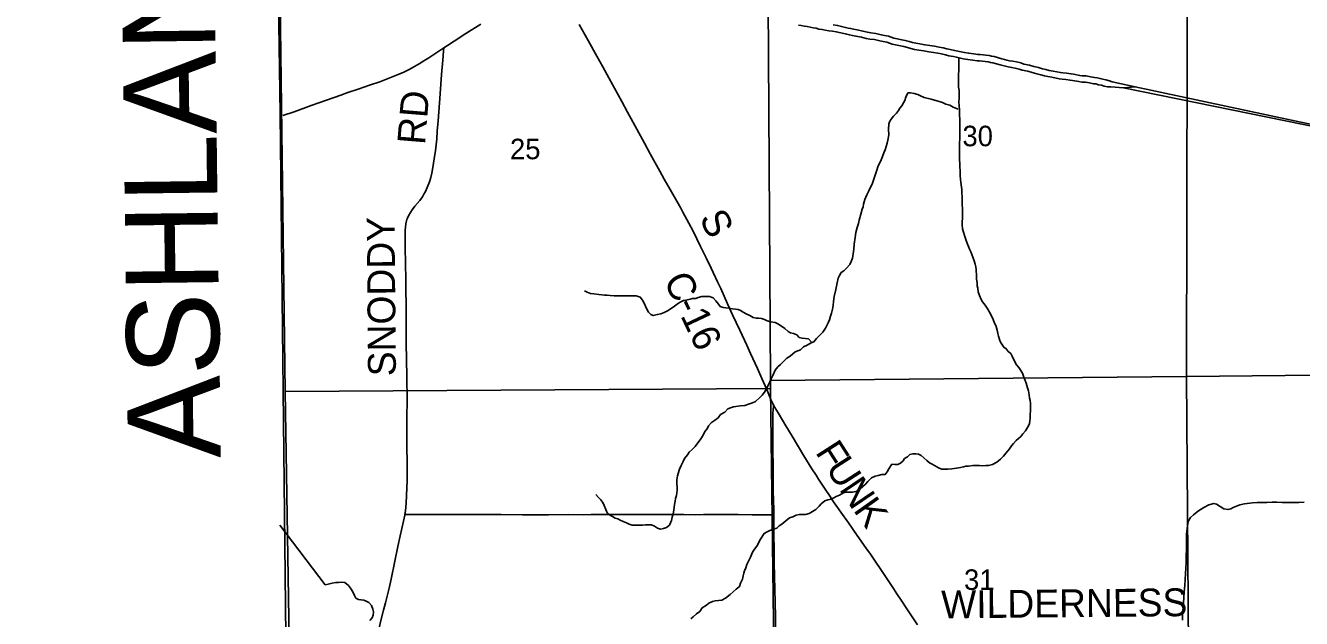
# Model space of a CAD drawing. Extents: x 1985906 to 2360102, y 891258 to 1222054.
# Drawn here: x 2069216 to 2082964, y 996240 to 1002629 of the extents above; entities that cross this region are included whole.
import ezdxf

# ---------------------------------------------------------------- set-up
doc = ezdxf.new("R2010")
doc.units = 0
for name, color, linetype in [('GM_X_Adjacent_County', 7, 'Continuous'), ('GM_X_Adjacent_County_Text', 7, 'Continuous'), ('GM_X_County', 7, 'Continuous'), ('GM_X_County_Road', 7, 'Continuous'), ('GM_X_County_Road_Text', 7, 'Continuous'), ('GM_X_Minor_River', 7, 'Continuous'), ('GM_X_Section', 7, 'Continuous'), ('GM_X_Section_Text', 7, 'Continuous'), ('GM_X_State_Route', 7, 'Continuous'), ('GM_X_Township', 7, 'Continuous'), ('GM_X_Township_Road', 7, 'Continuous'), ('GM_X_Township_Road_Text', 7, 'Continuous')]:
    doc.layers.add(name, color=color, linetype=linetype)

msp = doc.modelspace()

# ---------------------------------------------------------------- linework, layer by layer
at = {"layer": 'GM_X_Adjacent_County'}
msp.add_lwpolyline([(2071861, 1011952), (2071887, 1008769), (2071889, 1006520), (2071959, 1001676), (2072021, 996047), (2072065, 993379), (2071978, 993380), (2071988, 991894), (2071996, 990692), (2072013, 988008), (2072047, 982707), (2072077, 978079), (2072089, 977430), (2072091, 977317), (2072186, 972205), (2071957, 972211), (2068961, 972095)], dxfattribs=at)
at = {"layer": 'GM_X_County'}
msp.add_lwpolyline([(2072047, 982707), (2072013, 988008), (2071996, 990692), (2071988, 991894), (2071978, 993380), (2072065, 993379), (2072021, 996047), (2071959, 1001676), (2071889, 1006520), (2071887, 1008769), (2071861, 1011952)], dxfattribs=at)
at = {"layer": 'GM_X_County_Road'}
for points in [[(2077277, 998539), (2077268, 998556), (2077248, 998600), (2077204, 998706), (2077151, 998826), (2077103, 998932), (2077028, 999096), (2076987, 999185), (2076912, 999348), (2076834, 999512), (2076781, 999632), (2076707, 999795), (2076673, 999869), (2076605, 1000014), (2076551, 1000127), (2076490, 1000249), (2076408, 1000412), (2076362, 1000501), (2076299, 1000617), (2076276, 1000661), (2076219, 1000761), (2076162, 1000861), (2076098, 1000974), (2076050, 1001060), (2075946, 1001246), (2075884, 1001362), (2075782, 1001550), (2075703, 1001694), (2075641, 1001809), (2075521, 1002024), (2075435, 1002182), (2075373, 1002297), (2075278, 1002468), (2075182, 1002640)], [(2077278, 997358), (2077278, 997416), (2077276, 997515), (2077273, 997613), (2077271, 997777), (2077270, 997876), (2077268, 998056), (2077268, 998151), (2077269, 998285), (2077269, 998449), (2077270, 998493), (2077275, 998523), (2077277, 998539)], [(2078827, 996171), (2078711, 996346), (2078651, 996436), (2078605, 996505), (2078567, 996563), (2078512, 996649), (2078438, 996759), (2078365, 996867), (2078319, 996934), (2078272, 997002), (2078178, 997136), (2078131, 997203), (2078083, 997270), (2078000, 997385), (2077957, 997445), (2077923, 997496), (2077877, 997564), (2077832, 997633), (2077759, 997743), (2077734, 997784), (2077689, 997854), (2077603, 997993), (2077476, 998203), (2077408, 998315), (2077324, 998456), (2077291, 998512), (2077277, 998539)], [(2077298, 996101), (2077296, 996253), (2077292, 996418), (2077290, 996548), (2077287, 996699), (2077284, 996831), (2077281, 997007), (2077279, 997117), (2077278, 997230), (2077278, 997336), (2077278, 997358)]]:
    msp.add_lwpolyline(points, dxfattribs=at)
at = {"layer": 'GM_X_Minor_River'}
msp.add_line((2081048, 1001957), (2081172, 1001968), dxfattribs=at)
for points in [[(2077543, 1002634), (2077575, 1002628), (2077605, 1002622), (2077639, 1002617), (2077671, 1002611), (2077703, 1002605), (2077735, 1002599)], [(2077735, 1002599), (2077765, 1002591), (2077799, 1002585), (2077832, 1002579), (2077870, 1002573), (2077910, 1002568), (2077952, 1002562), (2078064, 1002534), (2078094, 1002528), (2078126, 1002522), (2078164, 1002515), (2078223, 1002503), (2078273, 1002489), (2078315, 1002483), (2078365, 1002477), (2078421, 1002464), (2078457, 1002456), (2078497, 1002448), (2078554, 1002428), (2078678, 1002403), (2078718, 1002391), (2078756, 1002381), (2078796, 1002371), (2078843, 1002363), (2078895, 1002355), (2078949, 1002346), (2078999, 1002338), (2079047, 1002330), (2079087, 1002322), (2079127, 1002312), (2079165, 1002302), (2079214, 1002295), (2079246, 1002287), (2079320, 1002271), (2079368, 1002263), (2079394, 1002259), (2079424, 1002255), (2079470, 1002250), (2079496, 1002248), (2079526, 1002244), (2079557, 1002242), (2079587, 1002238), (2079613, 1002232), (2079639, 1002228), (2079717, 1002205), (2079747, 1002197), (2079775, 1002191), (2079805, 1002183), (2079841, 1002177), (2079878, 1002169), (2079922, 1002159), (2079954, 1002147), (2080016, 1002136), (2080064, 1002122), (2080112, 1002110), (2080156, 1002096), (2080195, 1002088), (2080233, 1002078), (2080275, 1002071), (2080355, 1002055), (2080385, 1002051), (2080425, 1002047), (2080471, 1002039), (2080497, 1002036), (2080566, 1002024), (2080596, 1002020), (2080636, 1002018), (2080680, 1002010), (2080722, 1002002), (2080750, 1001999), (2080778, 1001991), (2080808, 1001985), (2080840, 1001977), (2080874, 1001969), (2080910, 1001968), (2081048, 1001957)], [(2081172, 1001968), (2080925, 1002022), (2080895, 1002034), (2080856, 1002043), (2080823, 1002051), (2080794, 1002057), (2080764, 1002065), (2080733, 1002070), (2080692, 1002077), (2080643, 1002086), (2080602, 1002088), (2080576, 1002091), (2080508, 1002103), (2080482, 1002107), (2080434, 1002115), (2080393, 1002119), (2080366, 1002122), (2080288, 1002137), (2080247, 1002145), (2080210, 1002155), (2080174, 1002162), (2080131, 1002176), (2080082, 1002188), (2080032, 1002202), (2079972, 1002213), (2079941, 1002225), (2079892, 1002236), (2079854, 1002244), (2079819, 1002250), (2079791, 1002257), (2079763, 1002263), (2079736, 1002270), (2079654, 1002295), (2079625, 1002299), (2079598, 1002305), (2079563, 1002310), (2079533, 1002312), (2079503, 1002315), (2079477, 1002317), (2079433, 1002323), (2079404, 1002327), (2079379, 1002330), (2079332, 1002338), (2079261, 1002353), (2079227, 1002361), (2079179, 1002369), (2079144, 1002378), (2079102, 1002389), (2079059, 1002397), (2079010, 1002405), (2078960, 1002413), (2078906, 1002422), (2078853, 1002430), (2078810, 1002438), (2078773, 1002447), (2078736, 1002456), (2078695, 1002469), (2078572, 1002494), (2078515, 1002514), (2078471, 1002522), (2078437, 1002530), (2078377, 1002544), (2078324, 1002551), (2078287, 1002556), (2078238, 1002569), (2078178, 1002581), (2078139, 1002589), (2078107, 1002595), (2078079, 1002601), (2077965, 1002629), (2077919, 1002635)], [(2079274, 1002281), (2079267, 1001966), (2079275, 1001930), (2079277, 1001898), (2079275, 1001843), (2079273, 1001805), (2079275, 1001765), (2079278, 1001719), (2079278, 1001667), (2079282, 1001615), (2079284, 1001568), (2079284, 1001450), (2079282, 1001408), (2079280, 1001364), (2079279, 1001315), (2079279, 1001263), (2079281, 1001221), (2079281, 1001183), (2079283, 1001141), (2079283, 1001101), (2079285, 1001068), (2079287, 1001038), (2079287, 1001012), (2079291, 1000968), (2079294, 1000942), (2079300, 1000888), (2079304, 1000862), (2079306, 1000827), (2079308, 1000783), (2079308, 1000693), (2079310, 1000661), (2079310, 1000629), (2079312, 1000597), (2079311, 1000556), (2079309, 1000510), (2079309, 1000482), (2079311, 1000440), (2079321, 1000404), (2079335, 1000366), (2079349, 1000324), (2079366, 1000273), (2079376, 1000247), (2079386, 1000221), (2079400, 1000189), (2079422, 1000133), (2079437, 1000095), (2079449, 1000056), (2079455, 1000030), (2079459, 1000000), (2079463, 999928), (2079463, 999896), (2079469, 999856), (2079471, 999825), (2079476, 999799), (2079482, 999761), (2079494, 999719), (2079514, 999677), (2079528, 999651), (2079555, 999617), (2079577, 999584), (2079603, 999542), (2079636, 999478), (2079654, 999432), (2079674, 999386), (2079684, 999348), (2079692, 999311), (2079700, 999281), (2079709, 999245), (2079723, 999219), (2079757, 999163), (2079783, 999147), (2079804, 999117), (2079832, 999096), (2079848, 999066), (2079876, 999004), (2079895, 998972), (2079917, 998944), (2079957, 998884), (2079972, 998841), (2079986, 998803), (2079998, 998775), (2080012, 998725), (2080024, 998693), (2080030, 998651), (2080033, 998614), (2080041, 998588), (2080045, 998560), (2080045, 998522), (2080043, 998476), (2080041, 998442), (2080041, 998398), (2080037, 998368), (2080033, 998339), (2080013, 998297), (2079989, 998263), (2079963, 998231), (2079939, 998201), (2079891, 998157), (2079860, 998127), (2079840, 998101), (2079820, 998068)], [(2079265, 1001727), (2079213, 1001749), (2079175, 1001769), (2079134, 1001781), (2079098, 1001801), (2079048, 1001815), (2079011, 1001826), (2078973, 1001836), (2078900, 1001854), (2078860, 1001872), (2078830, 1001886), (2078791, 1001898), (2078753, 1001904), (2078723, 1001902), (2078701, 1001858), (2078689, 1001822), (2078677, 1001794), (2078657, 1001765), (2078635, 1001739), (2078621, 1001713), (2078599, 1001683), (2078570, 1001651), (2078542, 1001621), (2078526, 1001591), (2078518, 1001565), (2078514, 1001513), (2078519, 1001450), (2078509, 1001394), (2078501, 1001362), (2078479, 1001288), (2078463, 1001256), (2078451, 1001219), (2078437, 1001183), (2078400, 1001107), (2078388, 1001069), (2078374, 1001029), (2078360, 1000983), (2078342, 1000932), (2078302, 1000848), (2078284, 1000812), (2078270, 1000780), (2078260, 1000754), (2078246, 1000704), (2078240, 1000677), (2078232, 1000649), (2078216, 1000597), (2078200, 1000533), (2078190, 1000495), (2078176, 1000451), (2078164, 1000398), (2078154, 1000344), (2078145, 1000274), (2078141, 1000218), (2078135, 1000168), (2078127, 1000123), (2078113, 1000087), (2078097, 1000055), (2078061, 1000015), (2078034, 999987), (2078006, 999967), (2077988, 999935), (2077972, 999907), (2077960, 999856), (2077954, 999822), (2077946, 999786), (2077930, 999710), (2077922, 999654), (2077918, 999611), (2077912, 999573), (2077901, 999529), (2077891, 999497), (2077879, 999459), (2077864, 999425), (2077850, 999397), (2077834, 999367), (2077806, 999326), (2077782, 999300), (2077740, 999258), (2077710, 999220), (2077682, 999210), (2077639, 999184), (2077599, 999166), (2077565, 999136), (2077507, 999112), (2077454, 999066), (2077420, 999044), (2077350, 998975), (2077322, 998951), (2077295, 998915), (2077269, 998857), (2077251, 998823), (2077237, 998791), (2077223, 998761), (2077207, 998730), (2077177, 998678), (2077153, 998646), (2077127, 998620), (2077081, 998578), (2077048, 998562), (2077006, 998550), (2076968, 998534)], [(2083373, 1001484), (2081048, 1001957)], [(2081172, 1001968), (2083345, 1001506)], [(2077690, 999213), (2077651, 999252), (2077583, 999260), (2077553, 999266), (2077526, 999298), (2077492, 999309), (2077460, 999319), (2077434, 999331), (2077397, 999363), (2077361, 999389), (2077322, 999415), (2077292, 999429), (2077248, 999437), (2077208, 999447), (2077179, 999461), (2077147, 999473), (2077115, 999477), (2077087, 999477), (2077056, 999483), (2077020, 999504), (2076982, 999524), (2076947, 999542), (2076919, 999558), (2076893, 999568), (2076865, 999572), (2076834, 999576), (2076802, 999582), (2076760, 999586), (2076734, 999590), (2076701, 999600), (2076681, 999626), (2076653, 999664), (2076625, 999694), (2076584, 999711), (2076532, 999711), (2076504, 999709), (2076465, 999697), (2076439, 999689), (2076403, 999689), (2076377, 999681), (2076332, 999671), (2076304, 999665), (2076278, 999653), (2076250, 999636), (2076208, 999604), (2076163, 999574), (2076133, 999554), (2076097, 999538), (2076063, 999524), (2076023, 999514), (2075980, 999504), (2075952, 999514), (2075930, 999542), (2075912, 999574), (2075879, 999643), (2075863, 999671), (2075839, 999701), (2075796, 999715), (2075766, 999715), (2075726, 999717), (2075698, 999715), (2075663, 999717), (2075631, 999715), (2075559, 999715), (2075514, 999721), (2075484, 999723), (2075456, 999725), (2075426, 999727), (2075393, 999731), (2075339, 999739), (2075303, 999741), (2075266, 999755), (2075240, 999770)], [(2076968, 998534), (2076920, 998530), (2076845, 998520), (2076813, 998510), (2076785, 998498), (2076750, 998464), (2076706, 998438), (2076678, 998401), (2076638, 998373), (2076606, 998351), (2076576, 998317), (2076559, 998285), (2076537, 998255), (2076517, 998215), (2076491, 998177), (2076473, 998151), (2076451, 998120), (2076433, 998094), (2076399, 998060), (2076365, 998032), (2076347, 998004), (2076316, 997964), (2076302, 997930), (2076282, 997888), (2076264, 997849), (2076248, 997803), (2076242, 997777), (2076234, 997735), (2076234, 997691), (2076239, 997659), (2076237, 997623), (2076231, 997564), (2076221, 997534), (2076215, 997506), (2076207, 997470), (2076205, 997438), (2076203, 997408), (2076195, 997366), (2076185, 997332), (2076177, 997297), (2076153, 997245), (2076123, 997221), (2076091, 997209), (2076056, 997203), (2076024, 997215), (2075994, 997235), (2075962, 997251), (2075935, 997251), (2075897, 997249), (2075865, 997245), (2075798, 997245), (2075752, 997247), (2075720, 997255), (2075693, 997270), (2075655, 997286), (2075623, 997300), (2075597, 997314), (2075570, 997322), (2075542, 997338), (2075508, 997358), (2075482, 997380), (2075467, 997416), (2075451, 997456), (2075439, 997482), (2075415, 997517), (2075391, 997545), (2075360, 997575)], [(2079820, 998068), (2079784, 998024), (2079752, 997988), (2079722, 997956), (2079680, 997924), (2079635, 997900), (2079593, 997888), (2079563, 997888), (2079531, 997886), (2079494, 997888), (2079460, 997890), (2079422, 997888), (2079375, 997882), (2079347, 997880), (2079321, 997874), (2079291, 997868), (2079247, 997860), (2079198, 997854), (2079152, 997850), (2079116, 997848), (2079089, 997850), (2079061, 997858), (2079035, 997874), (2078986, 997902), (2078956, 997916), (2078926, 997944), (2078865, 997997), (2078837, 998011), (2078809, 998015), (2078777, 998015), (2078746, 998007), (2078718, 997981), (2078688, 997963), (2078672, 997937), (2078642, 997912), (2078614, 997900), (2078583, 997898), (2078551, 997902), (2078519, 997852), (2078499, 997820), (2078479, 997792), (2078441, 997790), (2078402, 997782), (2078370, 997772), (2078332, 997756), (2078290, 997716), (2078266, 997688), (2078239, 997662), (2078209, 997636), (2078167, 997610), (2078123, 997600), (2078089, 997600), (2078056, 997602), (2078030, 997594), (2077986, 997570), (2077952, 997553), (2077925, 997541), (2077895, 997525), (2077859, 997517), (2077829, 997509), (2077789, 997475), (2077768, 997449), (2077732, 997415), (2077694, 997393), (2077658, 997373), (2077620, 997361), (2077579, 997361), (2077553, 997359), (2077521, 997353), (2077483, 997335), (2077446, 997323), (2077410, 997291), (2077364, 997255), (2077338, 997239), (2077310, 997214), (2077263, 997198), (2077235, 997188), (2077207, 997174), (2077173, 997156), (2077137, 997096), (2077097, 997020), (2077070, 996988), (2077050, 996954), (2077026, 996901), (2077002, 996851), (2076988, 996821), (2076976, 996785), (2076962, 996755), (2076954, 996727), (2076948, 996701), (2076940, 996665), (2076920, 996620), (2076910, 996584), (2076874, 996556), (2076842, 996528), (2076808, 996498), (2076759, 996458), (2076719, 996438), (2076647, 996430), (2076618, 996424), (2076578, 996404)], [(2082020, 997479), (2081966, 997463), (2081911, 997437), (2081853, 997401), (2081801, 997357), (2081767, 997327), (2081744, 997284), (2081735, 997234), (2081727, 997152), (2081725, 997098), (2081725, 997064), (2081727, 997017), (2081725, 996971), (2081723, 996927), (2081723, 996843), (2081719, 996780), (2081716, 996724), (2081712, 996662), (2081706, 996594), (2081702, 996529), (2081698, 996467), (2081690, 996347), (2081684, 996285), (2081681, 996222)], [(2082993, 997495), (2082935, 997491), (2082876, 997489), (2082816, 997489), (2082756, 997491), (2082697, 997493), (2082647, 997493), (2082590, 997491), (2082540, 997491), (2082486, 997489), (2082437, 997487), (2082349, 997475), (2082300, 997463), (2082264, 997449), (2082230, 997435), (2082204, 997423), (2082173, 997413), (2082129, 997421), (2082048, 997473), (2082020, 997479)], [(2071957, 997245), (2072443, 996603)], [(2072443, 996603), (2072477, 996611), (2072521, 996621), (2072560, 996627), (2072588, 996629), (2072624, 996631), (2072658, 996629), (2072695, 996594), (2072717, 996566), (2072741, 996528), (2072760, 996488), (2072776, 996460), (2072804, 996444), (2072830, 996442), (2072860, 996436), (2072887, 996426), (2072915, 996414), (2072945, 996380), (2072959, 996339), (2072965, 996311), (2072962, 996277), (2072950, 996249), (2072925, 996219)], [(2076578, 996404), (2076552, 996384), (2076508, 996356), (2076480, 996317), (2076447, 996289), (2076411, 996257), (2076385, 996235)]]:
    msp.add_lwpolyline(points, dxfattribs=at)
at = {"layer": 'GM_X_Section'}
for points in [[(2077214, 1004148), (2081735, 1004192), (2081724, 998849), (2077242, 998805), (2077211, 1004046)], [(2081735, 1004192), (2087061, 1004218), (2087034, 998903), (2081724, 998849)], [(2077211, 1004046), (2077242, 998805), (2077244, 998717), (2072012, 998684), (2071944, 1004005)], [(2077242, 998805), (2081724, 998849), (2081764, 993479), (2081426, 993475), (2077312, 993413), (2077244, 998717)], [(2081724, 998849), (2087034, 998903), (2087037, 993541), (2086772, 993543), (2081764, 993479)], [(2072012, 998684), (2077244, 998717), (2077312, 993413), (2072100, 993357)]]:
    msp.add_lwpolyline(points, close=True, dxfattribs=at)
at = {"layer": 'GM_X_State_Route'}
msp.add_lwpolyline([(2071990, 1001659), (2072109, 1001699), (2072295, 1001766), (2072458, 1001824), (2072613, 1001879), (2072690, 1001906), (2072799, 1001943), (2072924, 1001985), (2073032, 1002023), (2073124, 1002058), (2073230, 1002101), (2073291, 1002127), (2073350, 1002155), (2073407, 1002186), (2073458, 1002216), (2073509, 1002247), (2073561, 1002281), (2073657, 1002344), (2073723, 1002388), (2073764, 1002414), (2073835, 1002461), (2073960, 1002541), (2074122, 1002642)], dxfattribs=at)
at = {"layer": 'GM_X_Township'}
msp.add_lwpolyline([(2093403, 993551), (2092330, 993551), (2087014, 993524), (2086787, 993555), (2085700, 993551), (2084443, 993529), (2084245, 993501), (2081946, 993496), (2080673, 993508), (2077314, 993425), (2072381, 993382), (2072065, 993379), (2072021, 996047), (2071959, 1001676), (2071889, 1006520), (2071887, 1008769), (2071861, 1011952)], dxfattribs=at)
at = {"layer": 'GM_X_Township_Road'}
for points in [[(2073303, 997360), (2073309, 997401), (2073318, 997482), (2073322, 997564), (2073327, 997727), (2073328, 997809), (2073327, 997907), (2073324, 998104), (2073324, 998254), (2073325, 998403), (2073327, 998595), (2073326, 998840), (2073321, 999036), (2073318, 999200), (2073318, 999298), (2073317, 999494), (2073316, 999625), (2073314, 999773), (2073313, 999888), (2073310, 1000068), (2073308, 1000232), (2073308, 1000313), (2073308, 1000376), (2073308, 1000425), (2073311, 1000458), (2073315, 1000491), (2073322, 1000523), (2073326, 1000540), (2073332, 1000555), (2073347, 1000585), (2073363, 1000614), (2073381, 1000642), (2073411, 1000681), (2073463, 1000744), (2073492, 1000783), (2073509, 1000810), (2073525, 1000839), (2073545, 1000883), (2073568, 1000944), (2073582, 1000991), (2073593, 1001038), (2073609, 1001119), (2073624, 1001216), (2073632, 1001280), (2073646, 1001408), (2073652, 1001489), (2073661, 1001603), (2073683, 1001893), (2073699, 1002100), (2073712, 1002256), (2073720, 1002354), (2073723, 1002388)], [(2073004, 996034), (2073016, 996089), (2073046, 996217), (2073073, 996329), (2073094, 996408), (2073133, 996567), (2073154, 996663), (2073195, 996856), (2073229, 997016), (2073254, 997129), (2073289, 997289), (2073302, 997353), (2073303, 997360)], [(2073303, 997360), (2073313, 997360), (2073540, 997360), (2073655, 997359), (2073753, 997359), (2073884, 997359), (2073933, 997359), (2073982, 997360), (2074048, 997361), (2074178, 997361), (2074342, 997359), (2074571, 997358), (2074850, 997358), (2075063, 997359), (2075226, 997358), (2075309, 997359), (2075380, 997359), (2075436, 997359), (2075499, 997359), (2075575, 997359), (2075636, 997359), (2075696, 997359), (2075752, 997360), (2075798, 997360), (2075870, 997360), (2075933, 997360), (2076047, 997361), (2076161, 997360), (2076244, 997360), (2076308, 997359), (2076440, 997358), (2076520, 997359), (2076619, 997359), (2076815, 997360), (2076894, 997359), (2077044, 997358), (2077155, 997358), (2077269, 997358), (2077278, 997358)]]:
    msp.add_lwpolyline(points, dxfattribs=at)

# ---------------------------------------------------------------- texts
at = {"layer": 'GM_X_Adjacent_County_Text'}
msp.add_text('ASHLAND COUNTY', height=1000, rotation=90.7331, dxfattribs=at).set_placement((2071320, 997971))
at = {"layer": 'GM_X_County_Road_Text'}
for s, rotation, p in [('S', 296.5662, (2076471, 1000554)), ('C-16', 295.3623, (2076087, 999887)), ('F', 302.6826, (2077720, 998032)), ('U', 302.8043, (2077830, 997861)), ('N', 303.9791, (2077976, 997634)), ('K', 305.3071, (2078128, 997409))]:
    msp.add_text(s, height=300, rotation=rotation, dxfattribs=at).set_placement(p)
at = {"layer": 'GM_X_Section_Text'}
for s, p in [('30', (2079311, 1001328)), ('25', (2074436, 1001188)), ('31', (2079328, 996548))]:
    msp.add_text(s, height=221, rotation=0, dxfattribs=at).set_placement(p)
at = {"layer": 'GM_X_Township_Road_Text'}
for s, rotation, p in [('RD', 85.2796, (2073520, 1001338)), ('SNODDY', 90.4946, (2073207, 998851)), ('WILDERNESS', 0.5394, (2079083, 996241))]:
    msp.add_text(s, height=300, rotation=rotation, dxfattribs=at).set_placement(p)

doc.saveas('drawing.dxf')
